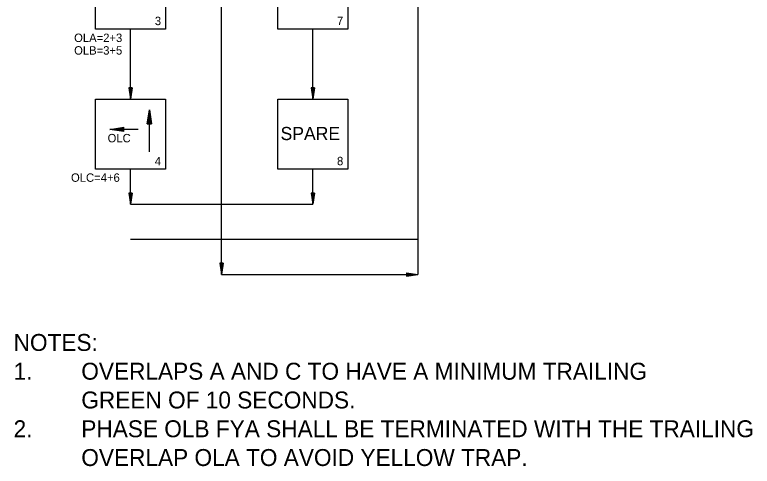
# Model space of a CAD drawing. Extents: x -218554 to 420030, y -565899 to -483460.
# Drawn here: x 418090.7 to 418273.8, y -565541.9 to -565429.8 of the extents above; entities that cross this region are included whole.
import ezdxf

# ---------------------------------------------------------------- set-up
doc = ezdxf.new("R2010")
doc.units = 0
doc.layers.add('G-ANNO-STMP', color=7, linetype='Continuous')
doc.layers.add('Level 57', color=7, linetype='Continuous')

msp = doc.modelspace()

# ---------------------------------------------------------------- linework, layer by layer
at = {"layer": 'Level 57'}
for p, q in [((418142.05, -565494.27), (418142.05, -565311.65)), ((418190.74, -565311.65), (418190.74, -565494.27)), ((418119.44, -565450.79), (418119.44, -565433.4)), ((418164.66, -565450.79), (418164.66, -565433.4)), ((418119.02, -565448.01), (418119.44, -565450.79)), ((418119.85, -565448.01), (418119.02, -565448.01)), ((418119.09, -565448.01), (418119.44, -565450.32)), ((418119.16, -565448.01), (418119.44, -565449.84)), ((418119.23, -565448.01), (418119.44, -565449.38)), ((418119.3, -565448.01), (418119.44, -565448.91)), ((418119.37, -565448.01), (418119.44, -565448.44)), ((418119.85, -565448.01), (418119.44, -565450.79)), ((418119.57, -565448.01), (418119.44, -565448.91)), ((418119.71, -565448.01), (418119.44, -565449.84)), ((418119.78, -565448.01), (418119.44, -565450.32)), ((418119.64, -565448.01), (418119.44, -565449.38)), ((418119.5, -565448.01), (418119.44, -565448.44)), ((418164.24, -565448.01), (418164.66, -565450.79)), ((418165.07, -565448.01), (418164.24, -565448.01)), ((418164.31, -565448.01), (418164.66, -565450.32)), ((418164.38, -565448.01), (418164.66, -565449.84)), ((418164.45, -565448.01), (418164.66, -565449.38)), ((418164.52, -565448.01), (418164.66, -565448.91)), ((418164.59, -565448.01), (418164.66, -565448.44)), ((418165.07, -565448.01), (418164.66, -565450.79)), ((418164.79, -565448.01), (418164.66, -565448.91)), ((418164.93, -565448.01), (418164.66, -565449.84)), ((418165, -565448.01), (418164.66, -565450.32)), ((418164.86, -565448.01), (418164.66, -565449.38)), ((418164.72, -565448.01), (418164.66, -565448.44)), ((418123.6, -565456.94), (418124.12, -565453.46)), ((418124.12, -565454.04), (418123.68, -565456.94)), ((418124.12, -565463.89), (418124.12, -565453.46)), ((418124.12, -565453.46), (418124.64, -565456.94)), ((418124.55, -565456.94), (418124.12, -565454.04)), ((418123.77, -565456.94), (418124.12, -565454.64)), ((418124.12, -565455.22), (418123.86, -565456.94)), ((418123.95, -565456.94), (418124.12, -565455.81)), ((418124.12, -565454.64), (418124.46, -565456.94)), ((418124.38, -565456.94), (418124.12, -565455.22)), ((418124.12, -565455.81), (418124.29, -565456.94)), ((418114.3, -565458.29), (418117.78, -565457.76)), ((418117.78, -565457.85), (418114.88, -565458.29)), ((418115.48, -565458.29), (418117.78, -565457.94)), ((418117.78, -565458.03), (418116.06, -565458.29)), ((418116.65, -565458.29), (418117.78, -565458.12)), ((418117.78, -565458.81), (418117.78, -565457.76)), ((418123.6, -565456.94), (418124.64, -565456.94)), ((418124.12, -565456.39), (418124.04, -565456.94)), ((418124.2, -565456.94), (418124.12, -565456.39)), ((418121.35, -565458.29), (418114.3, -565458.29)), ((418117.78, -565458.81), (418114.3, -565458.29)), ((418114.88, -565458.29), (418117.78, -565458.72)), ((418117.78, -565458.63), (418115.48, -565458.29)), ((418116.06, -565458.29), (418117.78, -565458.55)), ((418117.78, -565458.45), (418116.65, -565458.29)), ((418117.78, -565458.2), (418117.23, -565458.29)), ((418117.23, -565458.29), (418117.78, -565458.37)), ((418119.44, -565476.88), (418119.44, -565468.18)), ((418164.66, -565476.88), (418164.66, -565468.18)), ((418164.66, -565476.88), (418164.66, -565468.18)), ((418119.02, -565474.09), (418119.44, -565476.88)), ((418119.85, -565474.09), (418119.02, -565474.09)), ((418119.09, -565474.09), (418119.44, -565476.41)), ((418119.16, -565474.09), (418119.44, -565475.93)), ((418119.23, -565474.09), (418119.44, -565475.47)), ((418119.3, -565474.09), (418119.44, -565475)), ((418119.37, -565474.09), (418119.44, -565474.53)), ((418119.85, -565474.09), (418119.44, -565476.88)), ((418119.57, -565474.09), (418119.44, -565475)), ((418119.71, -565474.09), (418119.44, -565475.93)), ((418119.78, -565474.09), (418119.44, -565476.41)), ((418119.64, -565474.09), (418119.44, -565475.47)), ((418119.5, -565474.09), (418119.44, -565474.53)), ((418164.24, -565474.09), (418164.66, -565476.88)), ((418165.07, -565474.09), (418164.24, -565474.09)), ((418164.24, -565474.09), (418164.66, -565476.88)), ((418165.07, -565474.09), (418164.24, -565474.09)), ((418164.31, -565474.09), (418164.66, -565476.41)), ((418164.31, -565474.09), (418164.66, -565476.41)), ((418164.38, -565474.09), (418164.66, -565475.93)), ((418164.38, -565474.09), (418164.66, -565475.93)), ((418164.45, -565474.09), (418164.66, -565475.47)), ((418164.45, -565474.09), (418164.66, -565475.47)), ((418164.52, -565474.09), (418164.66, -565475)), ((418164.52, -565474.09), (418164.66, -565475)), ((418164.59, -565474.09), (418164.66, -565474.53)), ((418164.59, -565474.09), (418164.66, -565474.53)), ((418165.07, -565474.09), (418164.66, -565476.88)), ((418164.79, -565474.09), (418164.66, -565475)), ((418164.93, -565474.09), (418164.66, -565475.93)), ((418165, -565474.09), (418164.66, -565476.41)), ((418164.86, -565474.09), (418164.66, -565475.47)), ((418164.72, -565474.09), (418164.66, -565474.53)), ((418165.07, -565474.09), (418164.66, -565476.88)), ((418164.79, -565474.09), (418164.66, -565475)), ((418164.93, -565474.09), (418164.66, -565475.93)), ((418165, -565474.09), (418164.66, -565476.41)), ((418164.86, -565474.09), (418164.66, -565475.47)), ((418164.72, -565474.09), (418164.66, -565474.53)), ((418119.44, -565476.88), (418164.66, -565476.88)), ((418119.44, -565485.57), (418190.74, -565485.57)), ((418141.63, -565491.49), (418142.05, -565494.27)), ((418142.46, -565491.49), (418141.63, -565491.49)), ((418141.7, -565491.49), (418142.05, -565493.8)), ((418141.77, -565491.49), (418142.05, -565493.32)), ((418141.84, -565491.49), (418142.05, -565492.86)), ((418141.91, -565491.49), (418142.05, -565492.39)), ((418141.98, -565491.49), (418142.05, -565491.93)), ((418142.46, -565491.49), (418142.05, -565494.27)), ((418142.18, -565491.49), (418142.05, -565492.39)), ((418142.32, -565491.49), (418142.05, -565493.32)), ((418142.39, -565491.49), (418142.05, -565493.8)), ((418142.25, -565491.49), (418142.05, -565492.86)), ((418142.11, -565491.49), (418142.05, -565491.93)), ((418142.05, -565494.27), (418190.74, -565494.27)), ((418187.96, -565493.85), (418190.74, -565494.27)), ((418187.96, -565493.85), (418187.96, -565494.69)), ((418187.96, -565493.92), (418190.28, -565494.27)), ((418187.96, -565493.99), (418189.8, -565494.27)), ((418187.96, -565494.06), (418189.34, -565494.27)), ((418187.96, -565494.13), (418188.87, -565494.27)), ((418187.96, -565494.2), (418188.4, -565494.27)), ((418187.96, -565494.69), (418190.74, -565494.27)), ((418187.96, -565494.4), (418188.87, -565494.27)), ((418187.96, -565494.55), (418189.8, -565494.27)), ((418187.96, -565494.62), (418190.28, -565494.27)), ((418187.96, -565494.48), (418189.34, -565494.27)), ((418187.96, -565494.33), (418188.4, -565494.27))]:
    msp.add_line(p, q, dxfattribs=at)
for points in [[(418110.74, -565416), (418128.13, -565416), (418128.13, -565433.4), (418110.74, -565433.4)], [(418155.96, -565416), (418173.35, -565416), (418173.35, -565433.4), (418155.96, -565433.4)], [(418110.74, -565450.79), (418128.13, -565450.79), (418128.13, -565468.18), (418110.74, -565468.18)], [(418155.96, -565450.79), (418173.35, -565450.79), (418173.35, -565468.18), (418155.96, -565468.18)]]:
    msp.add_lwpolyline(points, close=True, dxfattribs=at)

# ---------------------------------------------------------------- texts
at = {"layer": 'G-ANNO-STMP'}
for s, p in [('NOTES:', (418090.41, -565513.26)), ('1.', (418090.41, -565520.4)), ('OVERLAPS A AND C TO HAVE A MINIMUM TRAILING', (418107.21, -565520.4)), ('GREEN OF 10 SECONDS.', (418107.21, -565527.54)), ('2.', (418090.41, -565534.68)), ('PHASE OLB FYA SHALL BE TERMINATED WITH THE TRAILING ', (418107.21, -565534.68)), ('OVERLAP OLA TO AVOID YELLOW TRAP.', (418107.21, -565541.82))]:
    msp.add_text(s, height=4.2, dxfattribs=at).set_placement(p)
at = {"layer": 'Level 57'}
for s, height, p in [('3', 2.09, (418125.46, -565432.41)), ('7', 2.09, (418170.68, -565432.41)), ('OLA=2+3', 2.087, (418105.43, -565436.6)), ('OLB=3+5', 2.087, (418105.43, -565439.73)), ('SPARE', 3.261, (418156.67, -565460.94)), ('OLC', 2.087, (418113.74, -565461.5)), ('4', 2.09, (418125.46, -565467.19)), ('8', 2.09, (418170.68, -565467.19)), ('OLC=4+6', 2.087, (418104.66, -565471.29))]:
    msp.add_text(s, height=height, dxfattribs=at).set_placement(p)

doc.saveas('drawing.dxf')
